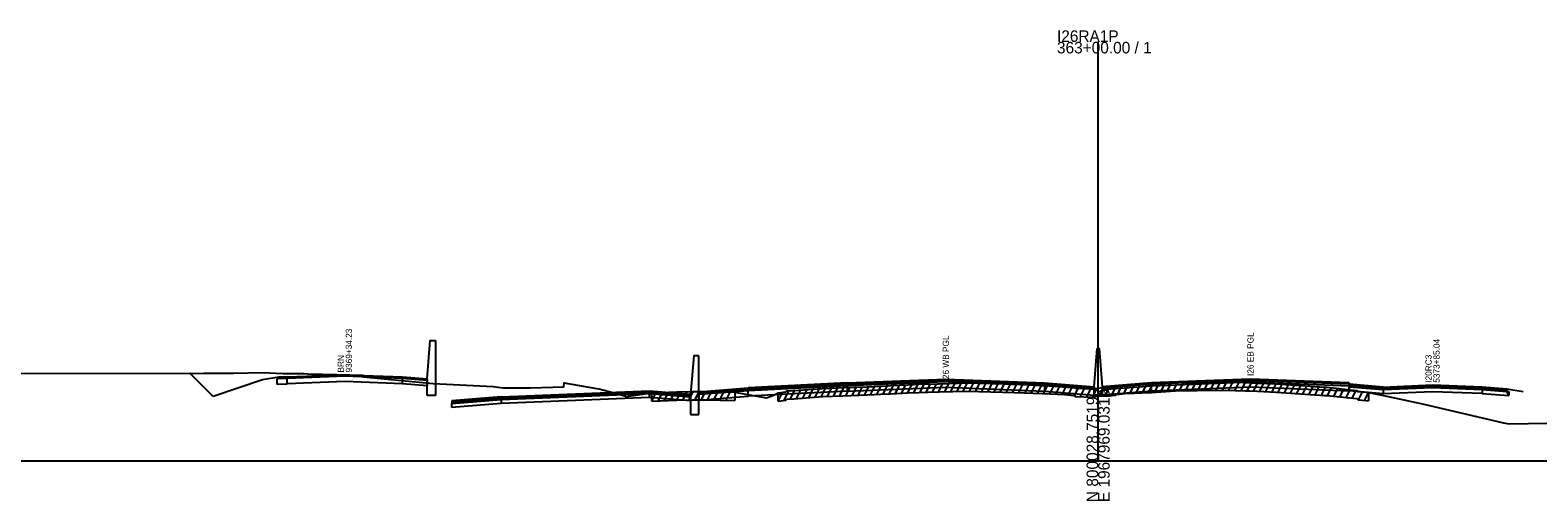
# Model space of a CAD drawing. Extents: x 1017 to 19997, y -1947 to 50737.
# Drawn here: x 14340.6 to 14706.8, y 12990.3 to 13104.6 of the extents above; entities that cross this region are included whole.
import ezdxf

# ---------------------------------------------------------------- set-up
doc = ezdxf.new("R2010")
doc.units = 0
for name, color, linetype in [('RD_GPK_XS_Cell', 7, 'Continuous'), ('RD_XS_Base', 7, 'Continuous'), ('RD_XS_ExGround', 7, 'Continuous'), ('RD_XS_ExPaveRet', 7, 'Continuous'), ('RD_XS_Greenside', 7, 'Continuous'), ('RD_XS_MedBWall', 7, 'Continuous'), ('RD_XS_Pave', 7, 'Continuous'), ('RD_XS_PaveOvlay', 7, 'Continuous'), ('RD_XS_TieSlope', 7, 'Continuous'), ('RD_XS_TX_Notes', 7, 'Continuous')]:
    doc.layers.add(name, color=color, linetype=linetype)

msp = doc.modelspace()

# ---------------------------------------------------------------- linework, layer by layer
at = {"layer": 'RD_GPK_XS_Cell'}
for p, q in [((14600, 13000), (14600, 13101.76)), ((14000, 13000), (14600, 13000)), ((14600, 13000), (15200, 13000))]:
    msp.add_line(p, q, dxfattribs=at)
at = {"layer": 'RD_XS_Base'}
for points in [[(14403, 13020.07), (14417, 13020.63), (14431, 13020.07)], [(14403, 13020.07), (14400.5, 13019.97)], [(14400.5, 13019.97), (14400.5, 13018.63)], [(14400.5, 13018.63), (14403, 13018.73)], [(14403, 13018.73), (14403, 13020.07)], [(14431, 13018.75), (14417, 13019.29), (14403, 13018.73)], [(14431, 13018.75), (14431, 13020.07)], [(14431, 13020.07), (14437, 13019.59)], [(14437, 13018.27), (14431, 13018.75)], [(14437, 13019.59), (14437, 13018.27)], [(14515, 13015.71), (14515, 13017.05)], [(14539.05, 13016.92), (14515, 13015.71)], [(14539.05, 13018.26), (14539.05, 13016.92)], [(14539.05, 13016.92), (14563, 13017.89), (14587, 13016.92)], [(14599, 13017.32), (14587, 13018.26)], [(14587, 13018.26), (14587, 13016.92)], [(14587, 13016.92), (14599, 13015.98)], [(14599, 13015.98), (14599, 13017.32)], [(14601, 13015.98), (14601, 13017.32)], [(14613, 13016.92), (14601, 13015.98)], [(14613, 13016.92), (14613, 13018.26)], [(14660.95, 13016.92), (14637, 13017.89), (14613, 13016.92)], [(14660.95, 13016.92), (14660.95, 13018.26)], [(14660.95, 13016.99), (14660.95, 13017.99)], [(14660.95, 13017.99), (14669.22, 13017.31)], [(14669.22, 13016.31), (14660.95, 13016.99)], [(14661, 13016.92), (14660.95, 13016.92)], [(14661, 13018.26), (14661, 13016.92)], [(14669.22, 13017.31), (14669.22, 13016.31)], [(14693.25, 13016.36), (14681.24, 13016.81), (14669.22, 13016.31)], [(14693.25, 13017.36), (14693.25, 13016.36)], [(14699.76, 13015.85), (14699.26, 13016.89), (14693.25, 13017.36)], [(14693.25, 13017.36), (14699.26, 13016.89), (14699.76, 13016.85)], [(14699.76, 13016.85), (14699.76, 13015.85)], [(14443, 13013.95), (14455, 13014.93)], [(14443, 13012.95), (14443, 13013.95)], [(14455, 13013.93), (14443, 13012.95)], [(14491, 13015.37), (14479, 13014.89), (14455, 13013.93)], [(14455, 13014.93), (14455, 13013.93)], [(14491, 13016.37), (14501, 13015.57)], [(14491, 13015.37), (14491, 13016.37)], [(14501, 13014.57), (14491, 13015.37)], [(14501, 13015.57), (14501, 13014.57)], [(14503, 13016.09), (14503, 13014.75)], [(14503, 13014.75), (14515, 13015.71)], [(14693.25, 13016.36), (14699.76, 13015.85)]]:
    msp.add_lwpolyline(points, dxfattribs=at)
at = {"layer": 'RD_XS_ExGround'}
msp.add_lwpolyline([(14329.42, 13021.21), (14382.67, 13021.34), (14387.86, 13021.32), (14389.64, 13021.33), (14389.97, 13021.33), (14397.04, 13021.46), (14401.95, 13021.22), (14404.23, 13021.19), (14405.81, 13021.19), (14407.07, 13021.23), (14408.12, 13021.11), (14409.01, 13021.08), (14411.46, 13021.05), (14415.03, 13020.97), (14421.32, 13020.8), (14421.42, 13020.4), (14438.49, 13018.81), (14453.03, 13018.06), (14455.48, 13017.76), (14462.11, 13017.77), (14470.2, 13018), (14470.3, 13019), (14478.13, 13017.6), (14478.81, 13017.47), (14483.32, 13016.26), (14485.2, 13015.73), (14485.59, 13015.65), (14486.01, 13015.72), (14491.62, 13016.54), (14497.64, 13016.74), (14501.49, 13016.83), (14504.56, 13016.83), (14511.74, 13016.69), (14513.89, 13016.33), (14519.44, 13015.34), (14521.24, 13015.95), (14522.24, 13016.52), (14524.11, 13016.75), (14524.4, 13016.99), (14526.05, 13017.11), (14533.07, 13017.61), (14537.95, 13017.8), (14543.89, 13018.03), (14547.15, 13018.19), (14549.68, 13018.32), (14553.77, 13018.51), (14556.48, 13018.64), (14561.01, 13018.76), (14561.41, 13018.76), (14568.14, 13018.95), (14573.96, 13018.78), (14579.7, 13018.65), (14586.48, 13018.34), (14591.82, 13018.09), (14594.17, 13017.87), (14594.62, 13017.65), (14598.42, 13017.5), (14600, 13017.69), (14601.08, 13017.82), (14601.86, 13017.83), (14602.9, 13017.84), (14603.4, 13017.89), (14604.19, 13017.95), (14604.42, 13018.13), (14607.29, 13018.44), (14608.75, 13018.49), (14612.51, 13018.61), (14612.95, 13018.64), (14618.72, 13018.98), (14624.08, 13019.08), (14630.85, 13019.2), (14635.8, 13019.03), (14636.89, 13018.99), (14638.75, 13018.92), (14643.25, 13018.71), (14655, 13017.92), (14655.62, 13017.88), (14656.38, 13017.8), (14662.75, 13017.13), (14663.15, 13016.85), (14665.01, 13016.68), (14665.7, 13016.6), (14669.73, 13015.78), (14674.3, 13014.82), (14679.14, 13013.82), (14698.46, 13009.26), (14699.85, 13008.97), (14718.31, 13009.37)], dxfattribs=at)
at = {"layer": 'RD_XS_ExPaveRet'}
for p, q in [((14494.62, 13014.64), (14495.64, 13016.67)), ((14496.12, 13014.69), (14497.14, 13016.72)), ((14497.62, 13014.74), (14498.63, 13016.76)), ((14499.12, 13014.77), (14500.13, 13016.8)), ((14500.62, 13014.81), (14501.63, 13016.83)), ((14502.12, 13014.83), (14503.12, 13016.83)), ((14503.62, 13014.83), (14504.62, 13016.83)), ((14505.12, 13014.82), (14506.11, 13016.8)), ((14506.62, 13014.79), (14507.61, 13016.77)), ((14508.12, 13014.76), (14509.11, 13016.74)), ((14509.62, 13014.73), (14510.61, 13016.72)), ((14511.74, 13016.69), (14511.74, 13014.69)), ((14523.74, 13014.7), (14524.9, 13017.03)), ((14525.24, 13015.05), (14526.27, 13017.12)), ((14526.74, 13015.16), (14527.78, 13017.23)), ((14528.24, 13015.26), (14529.28, 13017.34)), ((14529.74, 13015.37), (14530.78, 13017.45)), ((14531.24, 13015.48), (14532.28, 13017.55)), ((14532.74, 13015.59), (14533.76, 13017.64)), ((14534.24, 13015.66), (14535.26, 13017.69)), ((14535.74, 13015.71), (14536.76, 13017.75)), ((14537.24, 13015.77), (14538.26, 13017.81)), ((14538.74, 13015.83), (14539.76, 13017.87)), ((14540.24, 13015.89), (14541.26, 13017.93)), ((14541.74, 13015.94), (14542.76, 13017.98)), ((14543.24, 13016), (14544.26, 13018.05)), ((14544.74, 13016.07), (14545.77, 13018.12)), ((14546.24, 13016.15), (14547.26, 13018.2)), ((14547.74, 13016.22), (14548.76, 13018.27)), ((14549.24, 13016.3), (14550.26, 13018.35)), ((14550.74, 13016.37), (14551.76, 13018.42)), ((14552.24, 13016.44), (14553.26, 13018.49)), ((14553.74, 13016.51), (14554.76, 13018.56)), ((14555.24, 13016.58), (14556.26, 13018.63)), ((14556.48, 13016.64), (14561.01, 13016.76)), ((14556.74, 13016.64), (14557.75, 13018.67)), ((14558.24, 13016.68), (14559.25, 13018.71)), ((14559.74, 13016.72), (14560.75, 13018.75)), ((14561.01, 13016.76), (14561.41, 13016.76)), ((14561.24, 13016.76), (14562.25, 13018.79)), ((14561.41, 13016.76), (14568.14, 13016.95)), ((14562.74, 13016.8), (14563.75, 13018.83)), ((14564.24, 13016.84), (14565.25, 13018.87)), ((14565.74, 13016.88), (14566.75, 13018.91)), ((14567.24, 13016.92), (14568.25, 13018.95)), ((14568.14, 13016.95), (14573.96, 13016.78)), ((14568.74, 13016.93), (14569.72, 13018.9)), ((14570.24, 13016.89), (14571.22, 13018.86)), ((14571.74, 13016.84), (14572.72, 13018.81)), ((14573.24, 13016.8), (14574.23, 13018.77)), ((14573.96, 13016.78), (14579.7, 13016.65)), ((14574.74, 13016.76), (14575.73, 13018.74)), ((14576.24, 13016.73), (14577.23, 13018.7)), ((14577.74, 13016.69), (14578.73, 13018.67)), ((14579.24, 13016.66), (14580.22, 13018.62)), ((14580.74, 13016.6), (14581.72, 13018.56)), ((14582.24, 13016.53), (14583.22, 13018.49)), ((14583.74, 13016.46), (14584.72, 13018.42)), ((14585.24, 13016.4), (14586.22, 13018.35)), ((14586.74, 13016.33), (14587.72, 13018.28)), ((14588.24, 13016.26), (14589.22, 13018.21)), ((14589.74, 13016.19), (14590.72, 13018.14)), ((14591.24, 13016.12), (14592.21, 13018.05)), ((14592.74, 13016), (14593.69, 13017.91)), ((14594.24, 13015.83), (14595.14, 13017.63)), ((14595.74, 13015.61), (14596.72, 13017.57)), ((14597.24, 13015.55), (14598.22, 13017.51)), ((14598.74, 13015.54), (14599.8, 13017.67)), ((14600.24, 13015.72), (14601.29, 13017.82)), ((14601.74, 13015.83), (14602.74, 13017.84)), ((14603.24, 13015.87), (14604.34, 13018.06)), ((14604.74, 13016.16), (14605.8, 13018.28)), ((14606.24, 13016.33), (14607.3, 13018.44)), ((14607.74, 13016.46), (14608.76, 13018.49)), ((14609.24, 13016.51), (14610.26, 13018.54)), ((14610.74, 13016.55), (14611.76, 13018.58)), ((14612.24, 13016.6), (14613.27, 13018.65)), ((14612.95, 13016.64), (14618.72, 13016.98)), ((14613.74, 13016.68), (14614.77, 13018.74)), ((14615.24, 13016.77), (14616.27, 13018.83)), ((14616.74, 13016.86), (14617.77, 13018.92)), ((14618.24, 13016.95), (14619.26, 13018.99)), ((14618.72, 13016.98), (14624.08, 13017.08)), ((14619.74, 13017), (14620.75, 13019.02)), ((14621.24, 13017.03), (14622.25, 13019.05)), ((14622.74, 13017.06), (14623.75, 13019.07)), ((14624.08, 13017.08), (14630.85, 13017.2)), ((14624.24, 13017.08), (14625.25, 13019.1)), ((14625.74, 13017.11), (14626.75, 13019.13)), ((14627.24, 13017.14), (14628.25, 13019.15)), ((14628.74, 13017.16), (14629.75, 13019.18)), ((14630.24, 13017.19), (14631.24, 13019.19)), ((14630.85, 13017.2), (14635.8, 13017.03)), ((14631.74, 13017.17), (14632.72, 13019.13)), ((14633.24, 13017.12), (14634.22, 13019.08)), ((14634.74, 13017.06), (14635.72, 13019.03)), ((14635.8, 13017.03), (14636.89, 13016.99)), ((14636.24, 13017.01), (14637.22, 13018.98)), ((14636.89, 13016.99), (14638.75, 13016.92)), ((14637.74, 13016.96), (14638.72, 13018.92)), ((14638.75, 13016.92), (14643.25, 13016.71)), ((14639.24, 13016.9), (14640.22, 13018.85)), ((14640.74, 13016.83), (14641.72, 13018.78)), ((14642.24, 13016.76), (14643.22, 13018.71)), ((14643.25, 13016.71), (14655, 13015.92)), ((14643.74, 13016.68), (14644.71, 13018.61)), ((14645.24, 13016.57), (14646.21, 13018.51)), ((14646.74, 13016.47), (14647.71, 13018.41)), ((14648.24, 13016.37), (14649.21, 13018.31)), ((14649.74, 13016.27), (14650.71, 13018.21)), ((14651.24, 13016.17), (14652.21, 13018.11)), ((14652.74, 13016.07), (14653.71, 13018)), ((14654.24, 13015.97), (14655.21, 13017.9)), ((14655.74, 13015.86), (14656.69, 13017.76)), ((14657.24, 13015.71), (14658.19, 13017.61)), ((14658.74, 13015.55), (14659.69, 13017.45)), ((14660.24, 13015.39), (14661.19, 13017.3)), ((14661.74, 13015.24), (14662.69, 13017.14)), ((14663.24, 13014.84), (14664.2, 13016.75)), ((14491.62, 13014.54), (14492.64, 13016.58)), ((14491.62, 13014.54), (14491.62, 13016.54)), ((14491.62, 13014.54), (14497.64, 13014.74)), ((14493.12, 13014.59), (14494.14, 13016.62)), ((14497.64, 13014.74), (14501.49, 13014.83)), ((14501.49, 13014.83), (14504.56, 13014.83)), ((14504.56, 13014.83), (14511.74, 13014.69)), ((14522.24, 13014.52), (14523.3, 13016.65)), ((14522.24, 13014.52), (14522.24, 13016.52)), ((14522.24, 13014.52), (14524.11, 13014.75)), ((14524.11, 13014.75), (14524.4, 13014.99)), ((14524.4, 13014.99), (14526.05, 13015.11)), ((14526.05, 13015.11), (14533.07, 13015.61)), ((14533.07, 13015.61), (14537.95, 13015.8)), ((14537.95, 13015.8), (14543.89, 13016.03)), ((14543.89, 13016.03), (14547.15, 13016.19)), ((14547.15, 13016.19), (14549.68, 13016.32)), ((14549.68, 13016.32), (14553.77, 13016.51)), ((14553.77, 13016.51), (14556.48, 13016.64)), ((14579.7, 13016.65), (14586.48, 13016.34)), ((14586.48, 13016.34), (14591.82, 13016.09)), ((14591.82, 13016.09), (14594.17, 13015.87)), ((14594.17, 13015.87), (14594.62, 13015.65)), ((14594.62, 13015.65), (14598.42, 13015.5)), ((14598.42, 13015.5), (14600, 13015.69)), ((14600, 13015.69), (14601.08, 13015.82)), ((14601.08, 13015.82), (14601.86, 13015.83)), ((14601.86, 13015.83), (14602.9, 13015.84)), ((14602.9, 13015.84), (14603.4, 13015.89)), ((14603.4, 13015.89), (14604.19, 13015.95)), ((14604.19, 13015.95), (14604.42, 13016.13)), ((14604.42, 13016.13), (14607.29, 13016.44)), ((14607.29, 13016.44), (14608.75, 13016.49)), ((14608.75, 13016.49), (14612.51, 13016.61)), ((14612.51, 13016.61), (14612.95, 13016.64)), ((14655, 13015.92), (14655.62, 13015.88)), ((14655.62, 13015.88), (14656.38, 13015.8)), ((14656.38, 13015.8), (14662.75, 13015.13)), ((14662.75, 13015.13), (14663.15, 13014.85)), ((14663.15, 13014.85), (14665.01, 13014.68)), ((14664.74, 13014.7), (14665.69, 13016.6)), ((14665.01, 13014.68), (14665.7, 13014.6)), ((14665.7, 13016.6), (14665.7, 13014.6))]:
    msp.add_line(p, q, dxfattribs=at)
at = {"layer": 'RD_XS_Greenside'}
for points in [[(14397, 13019.66), (14385, 13015.66)], [(14401, 13020.3), (14397, 13019.66)], [(14699.26, 13017.53), (14703.27, 13016.89)]]:
    msp.add_lwpolyline(points, dxfattribs=at)
at = {"layer": 'RD_XS_MedBWall'}
for points in [[(14437, 13019.9), (14437.75, 13029.24), (14439, 13029.24)], [(14439, 13029.24), (14439, 13015.9)], [(14503, 13025.55), (14501.75, 13025.55), (14501, 13016.21)], [(14503, 13011.25), (14503, 13025.55)], [(14599, 13017.97), (14599.75, 13027.31)], [(14599.75, 13027.31), (14600.25, 13027.31), (14601, 13017.97)], [(14437, 13015.9), (14437, 13019.9)], [(14599, 13015.97), (14599, 13017.32), (14599, 13017.97)], [(14601, 13017.97), (14601, 13017.32), (14601, 13015.97)], [(14439, 13015.9), (14437, 13015.9)], [(14501, 13016.21), (14501, 13011.25)], [(14601, 13015.97), (14599, 13015.97)], [(14501, 13011.25), (14503, 13011.25)]]:
    msp.add_lwpolyline(points, dxfattribs=at)
at = {"layer": 'RD_XS_Pave'}
for points in [[(14491, 13016.69), (14479, 13016.21), (14455, 13015.25)], [(14491, 13016.37), (14491, 13016.69)], [(14491, 13016.69), (14501, 13015.89)], [(14503, 13016.43), (14515, 13017.39)], [(14515, 13017.05), (14503, 13016.09)], [(14515, 13017.39), (14539.05, 13018.6)], [(14539.05, 13018.26), (14515, 13017.05)], [(14515, 13017.05), (14515, 13017.39)], [(14587, 13018.26), (14563, 13019.23), (14539.05, 13018.26)], [(14539.05, 13018.6), (14539.05, 13018.26)], [(14587, 13018.6), (14587, 13018.26)], [(14587, 13018.6), (14599, 13017.66)], [(14599, 13017.66), (14599, 13017.32)], [(14613, 13018.6), (14601, 13017.66)], [(14601, 13017.32), (14613, 13018.26)], [(14601, 13017.66), (14601, 13017.32)], [(14660.95, 13018.6), (14637, 13019.56), (14613, 13018.6)], [(14613, 13018.26), (14637, 13019.23), (14660.95, 13018.26)], [(14613, 13018.26), (14613, 13018.6)], [(14660.95, 13018.6), (14661, 13018.6)], [(14660.95, 13018.26), (14660.95, 13018.6)], [(14669.22, 13017.63), (14660.95, 13018.32)], [(14660.95, 13018.32), (14660.95, 13017.99)], [(14661, 13018.26), (14660.95, 13018.26)], [(14661, 13018.6), (14661, 13018.26)], [(14693.25, 13017.68), (14681.24, 13018.13), (14669.22, 13017.63)], [(14669.22, 13017.31), (14681.24, 13017.81), (14693.25, 13017.36)], [(14669.22, 13017.63), (14669.22, 13017.31)], [(14693.25, 13017.36), (14693.25, 13017.68)], [(14693.25, 13017.68), (14699.26, 13017.21)], [(14699.26, 13016.89), (14693.25, 13017.36)], [(14699.26, 13017.21), (14699.26, 13016.89)], [(14455, 13015.25), (14443, 13014.29)], [(14443, 13014.29), (14443, 13013.95)], [(14455, 13014.93), (14479, 13015.89), (14491, 13016.37)], [(14455, 13015.25), (14455, 13014.93)], [(14501, 13015.89), (14501, 13015.57)], [(14503, 13016.09), (14503, 13016.43)]]:
    msp.add_lwpolyline(points, dxfattribs=at)
at = {"layer": 'RD_XS_PaveOvlay'}
for points in [[(14403, 13020.38), (14401, 13020.3)], [(14403, 13020.38), (14417, 13020.94), (14431, 13020.38)], [(14403, 13020.07), (14403, 13020.38)], [(14431, 13020.38), (14431, 13020.07)], [(14431, 13020.38), (14437, 13019.9)], [(14401, 13020.3), (14401, 13019.99)], [(14401, 13019.99), (14403, 13020.07)], [(14437, 13019.9), (14437, 13019.59)], [(14455, 13015.57), (14479, 13016.53), (14491, 13017.01)], [(14491, 13017.01), (14491, 13016.69)], [(14491, 13017.01), (14501, 13016.21)], [(14503, 13016.77), (14515, 13017.73)], [(14503, 13016.43), (14503, 13016.77)], [(14539.05, 13018.94), (14515, 13017.73)], [(14515, 13017.73), (14515, 13017.39)], [(14539.05, 13018.94), (14563, 13019.89), (14587, 13018.93)], [(14587, 13018.6), (14563, 13019.56), (14539.05, 13018.6)], [(14539.05, 13018.6), (14539.05, 13018.94)], [(14587, 13018.93), (14587, 13018.6)], [(14587, 13018.93), (14599, 13017.97)], [(14599, 13017.97), (14599, 13017.66)], [(14613, 13018.93), (14601, 13017.97)], [(14601, 13017.97), (14601, 13017.66)], [(14660.95, 13018.94), (14637, 13019.89), (14613, 13018.93)], [(14613, 13018.6), (14613, 13018.93)], [(14660.95, 13018.94), (14661, 13018.93)], [(14660.95, 13018.6), (14660.95, 13018.94)], [(14669.22, 13017.94), (14660.95, 13018.64)], [(14660.95, 13018.64), (14660.95, 13018.32)], [(14661, 13018.93), (14661, 13018.6)], [(14669.22, 13017.94), (14681.24, 13018.45), (14693.25, 13017.99)], [(14669.22, 13017.63), (14669.22, 13017.94)], [(14693.25, 13017.99), (14693.25, 13017.68)], [(14693.25, 13017.99), (14699.26, 13017.53)], [(14699.26, 13017.53), (14699.26, 13017.21)], [(14455, 13015.57), (14443, 13014.61)], [(14443, 13014.61), (14443, 13014.29)], [(14455, 13015.25), (14455, 13015.57)], [(14501, 13016.21), (14501, 13015.89)]]:
    msp.add_lwpolyline(points, dxfattribs=at)
at = {"layer": 'RD_XS_TieSlope'}
msp.add_lwpolyline([(14385, 13015.66), (14379.37, 13021.29)], dxfattribs=at)

# ---------------------------------------------------------------- texts
at = {"layer": 'RD_GPK_XS_Cell'}
for s, p in [('I26RA1P', (14590, 13101.76)), ('363+00.00 / 1', (14590, 13098.96))]:
    msp.add_text(s, height=2.8, dxfattribs=at).set_placement(p)
for s, p in [('E 1967969.0319', (14602.8, 12990)), ('N 800028.7519', (14600, 12990))]:
    msp.add_text(s, height=2.8, rotation=90, dxfattribs=at).set_placement(p)
at = {"layer": 'RD_XS_TX_Notes'}
for s, p in [(' 9369+34.23', (14418.73, 13020.91)), ('I26 WB PGL', (14563.75, 13019.31)), ('I26 EB PGL', (14637.75, 13020.63)), (' 5373+85.04', (14682.96, 13018.43)), (' BRN', (14416.77, 13020.91)), (' I20RC3', (14681.01, 13018.43))]:
    msp.add_text(s, height=1.5, rotation=90, dxfattribs=at).set_placement(p)

doc.saveas('drawing.dxf')
